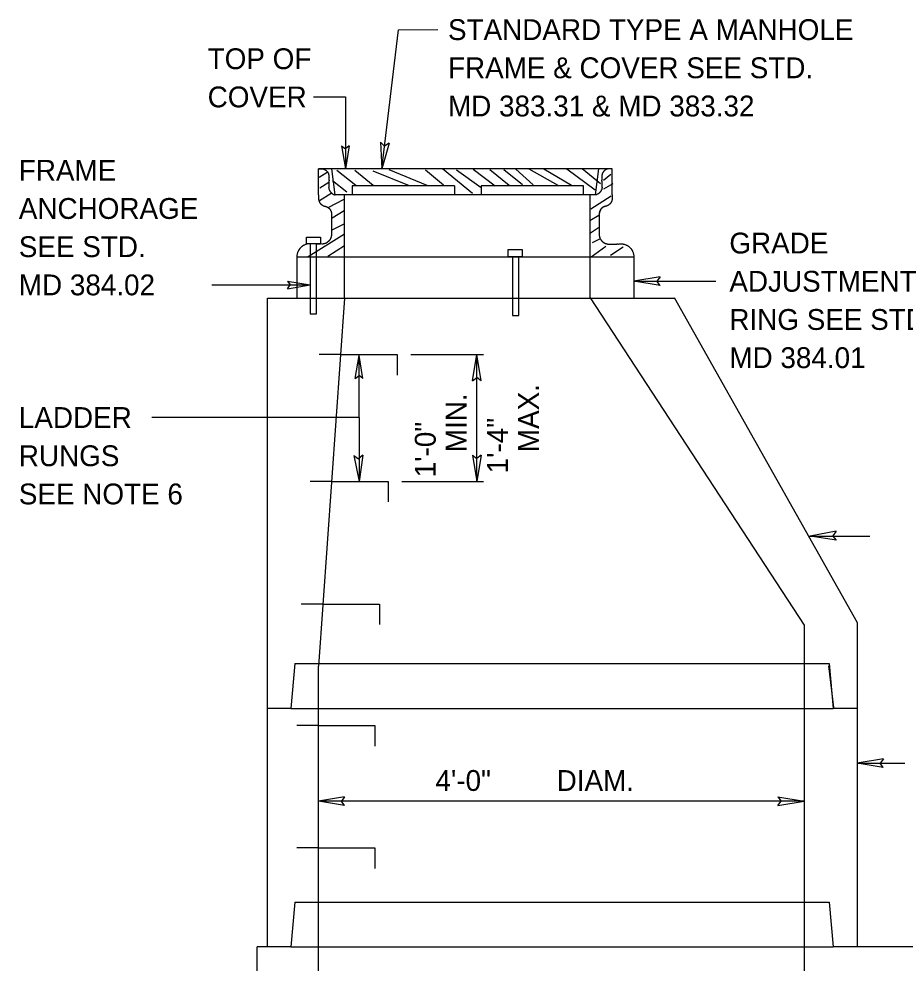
# Model space of a CAD drawing. Extents: x 26.41 to 33.74, y 20.66 to 30.6.
# Drawn here: x 26.466 to 29.019, y 25.68 to 28.398 of the extents above; entities that cross this region are included whole.
import ezdxf

# ---------------------------------------------------------------- set-up
doc = ezdxf.new("R2010")
doc.units = 0
for name, color, linetype in [('DETL-DIMS', 7, 'Continuous'), ('DETL-LINE', 7, 'Continuous'), ('DETL-NOTE', 7, 'Continuous'), ('DETL-PATT', 7, 'Continuous')]:
    doc.layers.add(name, color=color, linetype=linetype)

msp = doc.modelspace()

# ---------------------------------------------------------------- linework, layer by layer
at = {"layer": 'DETL-DIMS'}
for p, q in [((27.5113, 27.9666), (27.5597, 28.3669)), ((27.5597, 28.3669), (27.6727, 28.3672)), ((27.3149, 28.1734), (27.4069, 28.1734)), ((27.4069, 28.1734), (27.4069, 27.9666)), ((27.3959, 28.0326), (27.4069, 27.9666)), ((27.3959, 28.0326), (27.4069, 28.0244)), ((27.4179, 28.0326), (27.4069, 27.9666)), ((27.4179, 28.0326), (27.4069, 28.0244)), ((27.5079, 28.043), (27.5113, 27.9666)), ((27.5079, 28.043), (27.5193, 28.0321)), ((27.5329, 28.04), (27.5113, 27.9666)), ((27.5329, 28.04), (27.5193, 28.0321)), ((28.3128, 27.6553), (28.2373, 27.6427)), ((28.3128, 27.6553), (28.3034, 27.6427)), ((27.0221, 27.6323), (27.3056, 27.6323)), ((27.2395, 27.6433), (27.3056, 27.6323)), ((27.2395, 27.6433), (27.2478, 27.6323)), ((27.2395, 27.6213), (27.3056, 27.6323)), ((27.2395, 27.6213), (27.2478, 27.6323)), ((28.3128, 27.6302), (28.2373, 27.6427)), ((28.2373, 27.6427), (28.4732, 27.6427)), ((28.3128, 27.6302), (28.3034, 27.6427)), ((27.4349, 27.3631), (27.4459, 27.4292)), ((27.4459, 27.2504), (27.4459, 27.4292)), ((27.4569, 27.3631), (27.4459, 27.4292)), ((27.595, 27.4316), (27.8048, 27.4316)), ((27.7727, 27.3561), (27.7852, 27.4316)), ((27.7852, 27.0665), (27.7852, 27.4316)), ((27.7979, 27.3562), (27.7852, 27.4316)), ((27.4349, 27.3631), (27.4459, 27.3714)), ((27.4569, 27.3631), (27.4459, 27.3714)), ((27.7727, 27.3561), (27.7853, 27.3656)), ((27.7979, 27.3562), (27.7853, 27.3656)), ((27.4459, 27.2504), (26.8495, 27.2504)), ((27.4459, 27.2504), (27.4459, 27.066)), ((27.4314, 27.1411), (27.4459, 27.066)), ((27.4314, 27.1411), (27.4442, 27.132)), ((27.4566, 27.1417), (27.4442, 27.132)), ((27.4566, 27.1417), (27.4459, 27.066)), ((27.7727, 27.142), (27.7852, 27.0665)), ((27.7727, 27.142), (27.7853, 27.1325)), ((27.7979, 27.1419), (27.7852, 27.0665)), ((27.7979, 27.1419), (27.7853, 27.1325)), ((27.569, 27.0665), (27.8048, 27.0665)), ((28.8201, 26.9229), (28.7449, 26.909)), ((28.8201, 26.9229), (28.8109, 26.9102)), ((28.7406, 26.909), (28.9175, 26.909)), ((28.8206, 26.8978), (28.7449, 26.909)), ((28.8206, 26.8978), (28.8109, 26.9102)), ((28.956, 26.2682), (28.8805, 26.2558)), ((28.956, 26.2682), (28.9465, 26.2557)), ((28.9559, 26.2431), (28.8805, 26.2558)), ((28.8805, 26.2558), (29.018, 26.2558)), ((28.9559, 26.2431), (28.9465, 26.2557)), ((27.4044, 26.1587), (27.3289, 26.146)), ((27.4044, 26.1587), (27.395, 26.1461)), ((28.6523, 26.1584), (28.7278, 26.146)), ((28.6523, 26.1584), (28.6618, 26.1458)), ((27.4044, 26.1336), (27.3289, 26.146)), ((28.7278, 26.146), (27.3289, 26.146)), ((27.4044, 26.1336), (27.395, 26.1461)), ((28.6524, 26.1333), (28.7278, 26.146)), ((28.6524, 26.1333), (28.6618, 26.1458))]:
    msp.add_line(p, q, dxfattribs=at)
at = {"layer": 'DETL-LINE'}
for p, q in [((28.1749, 27.9666), (27.3295, 27.9666)), ((27.3295, 27.8919), (27.3295, 27.9666)), ((27.3773, 27.8913), (27.3678, 27.9666)), ((28.127, 27.8913), (28.1365, 27.9666)), ((28.1749, 27.8919), (28.1749, 27.9666)), ((27.4262, 27.9175), (27.4262, 27.8913)), ((27.721, 27.9175), (27.4262, 27.9175)), ((27.721, 27.9175), (27.721, 27.8913)), ((27.7972, 27.9175), (27.7972, 27.8913)), ((28.092, 27.9175), (27.7972, 27.9175)), ((28.092, 27.8913), (28.092, 27.9175)), ((28.1269, 27.8913), (27.3773, 27.8913)), ((27.4044, 27.5937), (27.4044, 27.8913)), ((28.1117, 27.5937), (28.1117, 27.8913)), ((27.3666, 27.8362), (27.3666, 27.7758)), ((28.1377, 27.8362), (28.1377, 27.7758)), ((27.2945, 27.7502), (27.2945, 27.7698)), ((27.2945, 27.7698), (27.3349, 27.7698)), ((27.3349, 27.7698), (27.3349, 27.7502)), ((27.3056, 27.7502), (27.2945, 27.7502)), ((27.3237, 27.7502), (27.3349, 27.7502)), ((27.8754, 27.7129), (27.8754, 27.7342)), ((27.8754, 27.7342), (27.9158, 27.7342)), ((27.9158, 27.7342), (27.9158, 27.7129)), ((27.267, 27.7129), (28.2373, 27.7129)), ((27.267, 27.7129), (27.267, 27.5937)), ((27.9158, 27.7129), (27.8754, 27.7129)), ((27.8878, 27.7129), (27.8878, 27.544)), ((27.906, 27.544), (27.906, 27.7129)), ((28.2373, 27.7129), (28.2373, 27.5937)), ((27.1819, 27.5937), (28.3532, 27.5937)), ((27.1819, 25.7264), (27.1819, 27.5937)), ((27.4044, 27.5937), (27.3289, 26.5347)), ((28.1117, 27.5952), (28.7278, 26.6524)), ((28.3532, 27.5964), (28.8805, 26.6608)), ((27.8878, 27.544), (27.906, 27.544)), ((27.3928, 27.4316), (27.3308, 27.4316)), ((27.3668, 27.0665), (27.3048, 27.0665)), ((27.3417, 26.7135), (27.2796, 26.7135)), ((28.7278, 26.6524), (28.7278, 25.4993)), ((28.8805, 26.6608), (28.8805, 25.7264)), ((27.2614, 26.5419), (27.2493, 26.413)), ((27.2614, 26.5419), (28.7996, 26.5419)), ((27.3289, 23.3764), (27.3289, 26.5347)), ((28.7981, 26.5358), (28.8128, 26.416)), ((28.7996, 26.5419), (28.8117, 26.413)), ((27.2493, 26.413), (27.1819, 26.413)), ((27.2493, 26.413), (28.8117, 26.413)), ((28.8805, 26.413), (28.8117, 26.413)), ((27.3289, 26.3635), (27.2669, 26.3635)), ((27.3289, 26.0114), (27.2669, 26.0114)), ((27.2614, 25.8552), (27.2493, 25.7264)), ((27.2614, 25.8552), (28.7996, 25.8552)), ((28.7996, 25.8552), (28.8117, 25.7264)), ((27.1526, 23.135), (27.1526, 25.7264)), ((27.2493, 25.7264), (27.1526, 25.7264)), ((27.2493, 25.7264), (28.8117, 25.7264)), ((29.276, 25.7264), (28.8117, 25.7264))]:
    msp.add_line(p, q, dxfattribs=at)
msp.add_lwpolyline([(27.3056, 27.7502), (27.3056, 27.5488), (27.3237, 27.5488), (27.3237, 27.7502)], close=True, dxfattribs=at)
for points in [[(27.3928, 27.4316), (27.5557, 27.4316), (27.5557, 27.3726)], [(27.3668, 27.0665), (27.5297, 27.0665), (27.5297, 27.0075)], [(27.3417, 26.7135), (27.5045, 26.7135), (27.5045, 26.6545)], [(27.3289, 26.3635), (27.4918, 26.3635), (27.4918, 26.3046)], [(27.3289, 26.0114), (27.4918, 26.0114), (27.4918, 25.9524)]]:
    msp.add_lwpolyline(points, dxfattribs=at)
msp.add_arc((28.1605, 27.8363), 0.0228, 100.5321, 180.1949, dxfattribs=at)
for points in [[(27.3295, 27.9666), (27.3389, 27.9663), (27.3435, 27.9657), (27.3464, 27.9647), (27.3478, 27.9639), (27.3494, 27.963), (27.351, 27.9618), (27.3521, 27.9608), (27.3528, 27.9601), (27.3532, 27.9598), (27.3536, 27.9592), (27.3542, 27.9585), (27.3548, 27.9578), (27.3553, 27.9571), (27.356, 27.9561), (27.3566, 27.9548), (27.357, 27.9541), (27.3576, 27.9526), (27.3582, 27.9507), (27.3586, 27.9492), (27.3588, 27.9474), (27.3588, 27.9457), (27.3593, 27.944), (27.3594, 27.941), (27.359, 27.9389), (27.3592, 27.9343), (27.3596, 27.9331), (27.3593, 27.9313), (27.3594, 27.9275), (27.359, 27.9263), (27.3591, 27.922), (27.3587, 27.9207), (27.3588, 27.9156), (27.3585, 27.914), (27.3586, 27.9114), (27.359, 27.9097), (27.3592, 27.9086), (27.3601, 27.9057), (27.3613, 27.9034), (27.362, 27.9019), (27.3629, 27.9009), (27.3639, 27.8994), (27.3649, 27.8984), (27.3656, 27.8977), (27.3662, 27.8972), (27.3668, 27.8965), (27.3675, 27.8958), (27.3692, 27.8948), (27.3708, 27.8938), (27.3716, 27.8934), (27.3722, 27.8931), (27.3732, 27.8926), (27.3748, 27.8919), (27.3773, 27.8913)], [(28.1749, 27.9666), (28.1654, 27.9663), (28.1608, 27.9657), (28.1579, 27.9647), (28.1565, 27.9639), (28.1549, 27.963), (28.1534, 27.9618), (28.1522, 27.9608), (28.1514, 27.9601), (28.1511, 27.9598), (28.1507, 27.9592), (28.15, 27.9585), (28.1496, 27.9578), (28.149, 27.9571), (28.1483, 27.9561), (28.1477, 27.9548), (28.1473, 27.9541), (28.1467, 27.9526), (28.1461, 27.9507), (28.1457, 27.9492), (28.1455, 27.9474), (28.1454, 27.9457), (28.145, 27.944), (28.1449, 27.941), (28.1453, 27.9389), (28.1451, 27.9343), (28.1446, 27.9331), (28.145, 27.9313), (28.1449, 27.9275), (28.1453, 27.9263), (28.1452, 27.922), (28.1456, 27.9207), (28.1454, 27.9156), (28.1459, 27.914), (28.1457, 27.9114), (28.1453, 27.9097), (28.1451, 27.9086), (28.1442, 27.9057), (28.1429, 27.9034), (28.1423, 27.9019), (28.1414, 27.9009), (28.1404, 27.8994), (28.1395, 27.8984), (28.1387, 27.8977), (28.1381, 27.8972), (28.1375, 27.8965), (28.1367, 27.8958), (28.1351, 27.8948), (28.1336, 27.8938), (28.1328, 27.8934), (28.1321, 27.8931), (28.1312, 27.8926), (28.1295, 27.8919), (28.1269, 27.8913)], [(27.3295, 27.8919), (27.3295, 27.8902), (27.3294, 27.8887), (27.3295, 27.8877), (27.3293, 27.8864), (27.3293, 27.8847), (27.3293, 27.8836), (27.3293, 27.8812), (27.3294, 27.8803), (27.3296, 27.8789), (27.3297, 27.8775), (27.33, 27.8757), (27.3303, 27.8743), (27.3307, 27.8733), (27.331, 27.8727), (27.3313, 27.8719), (27.332, 27.8705), (27.3329, 27.8689), (27.3339, 27.8675), (27.3347, 27.8663), (27.3358, 27.8653), (27.3365, 27.8645), (27.3371, 27.8641), (27.339, 27.8625), (27.3405, 27.8616), (27.3419, 27.8607), (27.3426, 27.8603), (27.344, 27.8598), (27.3449, 27.8595), (27.3461, 27.8591), (27.3477, 27.8588), (27.3494, 27.8584), (27.3517, 27.8577), (27.3527, 27.8574), (27.3534, 27.857), (27.3542, 27.8566), (27.3548, 27.8563), (27.3555, 27.8559), (27.3564, 27.8553), (27.3573, 27.8546), (27.3581, 27.854), (27.3592, 27.8531), (27.3601, 27.8523), (27.3605, 27.8518), (27.3619, 27.8502), (27.363, 27.8485), (27.3637, 27.8474), (27.3642, 27.8465), (27.3647, 27.8452), (27.3653, 27.8441), (27.3656, 27.8432), (27.3658, 27.8422), (27.3661, 27.8413), (27.3663, 27.8398), (27.3665, 27.8385), (27.3665, 27.8371), (27.3666, 27.8362)], [(28.1749, 27.8919), (28.1748, 27.8902), (28.1749, 27.8887), (28.1748, 27.8877), (28.1749, 27.8864), (28.175, 27.8847), (28.175, 27.8836), (28.175, 27.8812), (28.1749, 27.8803), (28.1748, 27.8789), (28.1746, 27.8775), (28.1743, 27.8757), (28.1739, 27.8743), (28.1736, 27.8733), (28.1734, 27.8727), (28.1729, 27.8719), (28.1724, 27.8705), (28.1714, 27.8689), (28.1704, 27.8675), (28.1696, 27.8663), (28.1685, 27.8653), (28.1678, 27.8645), (28.1673, 27.8641), (28.1654, 27.8625), (28.1638, 27.8616), (28.1624, 27.8607), (28.1616, 27.8603), (28.1603, 27.8598), (28.1595, 27.8595), (28.1582, 27.8591), (28.1567, 27.8588), (28.1549, 27.8584), (28.1526, 27.8577), (28.1517, 27.8574), (28.151, 27.857), (28.1502, 27.8566), (28.1496, 27.8563), (28.1488, 27.8559), (28.1478, 27.8553), (28.1469, 27.8546), (28.1462, 27.854), (28.1451, 27.8531), (28.1443, 27.8523), (28.1437, 27.8518), (28.1424, 27.8502), (28.1413, 27.8485), (28.1406, 27.8474), (28.1401, 27.8465), (28.1396, 27.8452), (28.139, 27.8441), (28.1387, 27.8432), (28.1384, 27.8422), (28.1383, 27.8413), (28.1379, 27.8398), (28.1378, 27.8385), (28.1377, 27.8371), (28.1377, 27.8362)], [(27.3666, 27.7758), (27.3661, 27.7721), (27.3656, 27.7703), (27.3651, 27.7686), (27.3644, 27.7669), (27.3637, 27.7654), (27.3631, 27.7642), (27.3625, 27.7632), (27.3617, 27.762), (27.3609, 27.7609), (27.3601, 27.7599), (27.3592, 27.7589), (27.3582, 27.7578), (27.3575, 27.7572), (27.3568, 27.7565), (27.356, 27.7559), (27.355, 27.7552), (27.3542, 27.7547), (27.3533, 27.7541), (27.3527, 27.7536), (27.3513, 27.7529), (27.3501, 27.7523), (27.3484, 27.7516), (27.3457, 27.7508), (27.3438, 27.7504), (27.3424, 27.75), (27.3347, 27.7501), (27.3328, 27.7502), (27.331, 27.7502), (27.3271, 27.7502), (27.3252, 27.7502), (27.3236, 27.7502), (27.3218, 27.7502), (27.3176, 27.7502), (27.3151, 27.7502), (27.3114, 27.7502), (27.3098, 27.7502), (27.3078, 27.7502), (27.3052, 27.7502), (27.3042, 27.7502), (27.3031, 27.7502), (27.301, 27.7502), (27.2997, 27.7502), (27.2969, 27.7501), (27.2943, 27.7495), (27.2916, 27.7483), (27.2887, 27.7471), (27.2873, 27.7465), (27.2862, 27.7459), (27.2855, 27.7456), (27.2846, 27.7449), (27.2833, 27.7442), (27.2824, 27.7436), (27.2813, 27.7427), (27.2802, 27.7418), (27.279, 27.7407), (27.2782, 27.7399), (27.2768, 27.7384), (27.2761, 27.7376), (27.2757, 27.7373), (27.2753, 27.7367), (27.2748, 27.7361), (27.2744, 27.7356), (27.2739, 27.735), (27.2734, 27.734), (27.273, 27.7332), (27.2723, 27.7323), (27.2717, 27.7314), (27.271, 27.7302), (27.2705, 27.7289), (27.2691, 27.7259), (27.2681, 27.7221), (27.2671, 27.7183), (27.267, 27.7129)], [(28.1377, 27.7758), (28.1382, 27.7721), (28.1387, 27.7703), (28.1392, 27.7686), (28.1399, 27.7669), (28.1406, 27.7654), (28.1412, 27.7642), (28.1419, 27.7632), (28.1425, 27.762), (28.1434, 27.7609), (28.1442, 27.7599), (28.1451, 27.7589), (28.1461, 27.7578), (28.1468, 27.7572), (28.1475, 27.7565), (28.1483, 27.7559), (28.1492, 27.7552), (28.15, 27.7547), (28.151, 27.7541), (28.1517, 27.7536), (28.153, 27.7529), (28.1543, 27.7523), (28.156, 27.7516), (28.1586, 27.7508), (28.1605, 27.7504), (28.162, 27.75), (28.1696, 27.7498), (28.1711, 27.7496), (28.1725, 27.7497), (28.1776, 27.7496), (28.1789, 27.7495), (28.1806, 27.7495), (28.1823, 27.7499), (28.1874, 27.7497), (28.1887, 27.7501), (28.1929, 27.75), (28.1942, 27.7499), (28.1959, 27.7504), (28.1993, 27.7502), (28.2001, 27.7506), (28.2012, 27.7504), (28.2033, 27.7503), (28.2046, 27.7502), (28.2068, 27.7499), (28.2098, 27.7492), (28.2126, 27.7483), (28.2156, 27.7471), (28.217, 27.7465), (28.2181, 27.7459), (28.2188, 27.7456), (28.2198, 27.7449), (28.221, 27.7442), (28.2219, 27.7436), (28.2231, 27.7427), (28.224, 27.7418), (28.2253, 27.7407), (28.2261, 27.7399), (28.2275, 27.7384), (28.2283, 27.7376), (28.2286, 27.7373), (28.229, 27.7367), (28.2295, 27.7361), (28.23, 27.7356), (28.2305, 27.735), (28.2309, 27.734), (28.2313, 27.7332), (28.232, 27.7323), (28.2326, 27.7314), (28.2332, 27.7302), (28.2339, 27.7289), (28.2352, 27.7259), (28.2363, 27.7221), (28.2372, 27.7183), (28.2373, 27.7129)]]:
    msp.add_spline(points, degree=3, dxfattribs=at)
at = {"layer": 'DETL-PATT'}
for p, q in [((27.3542, 27.9555), (27.3308, 27.9416)), ((27.4363, 27.9187), (27.3824, 27.9617)), ((27.4867, 27.9182), (27.4337, 27.9612)), ((27.5913, 27.9176), (27.4867, 27.9601)), ((27.6426, 27.9183), (27.5325, 27.9635)), ((27.6892, 27.9195), (27.6371, 27.9625)), ((27.7724, 27.8952), (27.6863, 27.9662)), ((27.7979, 27.9115), (27.7265, 27.963)), ((27.8379, 27.9167), (27.7748, 27.9642)), ((27.8782, 27.9186), (27.8231, 27.9633)), ((27.9167, 27.92), (27.8625, 27.9639)), ((27.9473, 27.9204), (27.8977, 27.965)), ((28.0193, 27.9187), (27.9358, 27.9656)), ((28.0578, 27.9189), (27.9786, 27.9658)), ((28.1257, 27.9051), (28.0447, 27.9654)), ((28.1409, 27.9233), (28.0888, 27.966)), ((28.1498, 27.9342), (28.171, 27.9514)), ((27.3327, 27.9116), (27.3588, 27.9285)), ((27.4107, 27.8991), (27.3698, 27.9316)), ((28.177, 27.9237), (28.1503, 27.9079)), ((27.366, 27.8953), (27.3322, 27.8747)), ((27.3571, 27.8547), (27.4031, 27.8795)), ((28.1131, 27.8513), (28.1718, 27.8887)), ((27.4034, 27.8452), (27.3687, 27.824)), ((28.1363, 27.8316), (28.1109, 27.8167)), ((27.3682, 27.7908), (27.403, 27.8083)), ((28.1121, 27.7824), (28.1358, 27.7973)), ((27.4038, 27.7779), (27.2993, 27.7133)), ((28.1408, 27.7646), (28.1172, 27.753)), ((27.3556, 27.7147), (27.4042, 27.7458)), ((28.1148, 27.7128), (28.1571, 27.7434)), ((28.1704, 27.718), (28.2067, 27.7416))]:
    msp.add_line(p, q, dxfattribs=at)

# ---------------------------------------------------------------- texts
at = {"layer": 'DETL-NOTE'}
for s, p in [('STANDARD TYPE A MANHOLE', (27.7021, 28.3372)), ('TOP OF', (27.01, 28.2534)), ('FRAME & COVER SEE STD.', (27.7021, 28.2273)), ('COVER', (27.01, 28.1434)), ('MD 383.31 & MD 383.32', (27.7021, 28.1173)), ('FRAME', (26.4661, 27.9322)), ('ANCHORAGE', (26.4661, 27.8223)), ('GRADE', (28.5125, 27.7227)), ('SEE STD.', (26.4661, 27.7123)), ('ADJUSTMENT', (28.5125, 27.6127)), ('MD 384.02', (26.4661, 27.6023)), ('RING SEE STD.', (28.5125, 27.5027)), ('MD 384.01', (28.5125, 27.3928)), ('LADDER', (26.4661, 27.2204)), ('RUNGS', (26.4661, 27.1104)), ('SEE NOTE 6', (26.4661, 27.0004)), ('4\'-0"', (27.6661, 26.1755)), ('DIAM.', (28.0151, 26.1755))]:
    msp.add_text(s, height=0.05998, dxfattribs=at).set_placement(p)
for s, p in [('MAX.', (27.9642, 27.1508)), ('MIN.', (27.7557, 27.1508)), ('1\'-4"', (27.8746, 27.0898)), ('1\'-0"', (27.6667, 27.0784))]:
    msp.add_text(s, height=0.05998, rotation=90, dxfattribs=at).set_placement(p)

doc.saveas('drawing.dxf')
